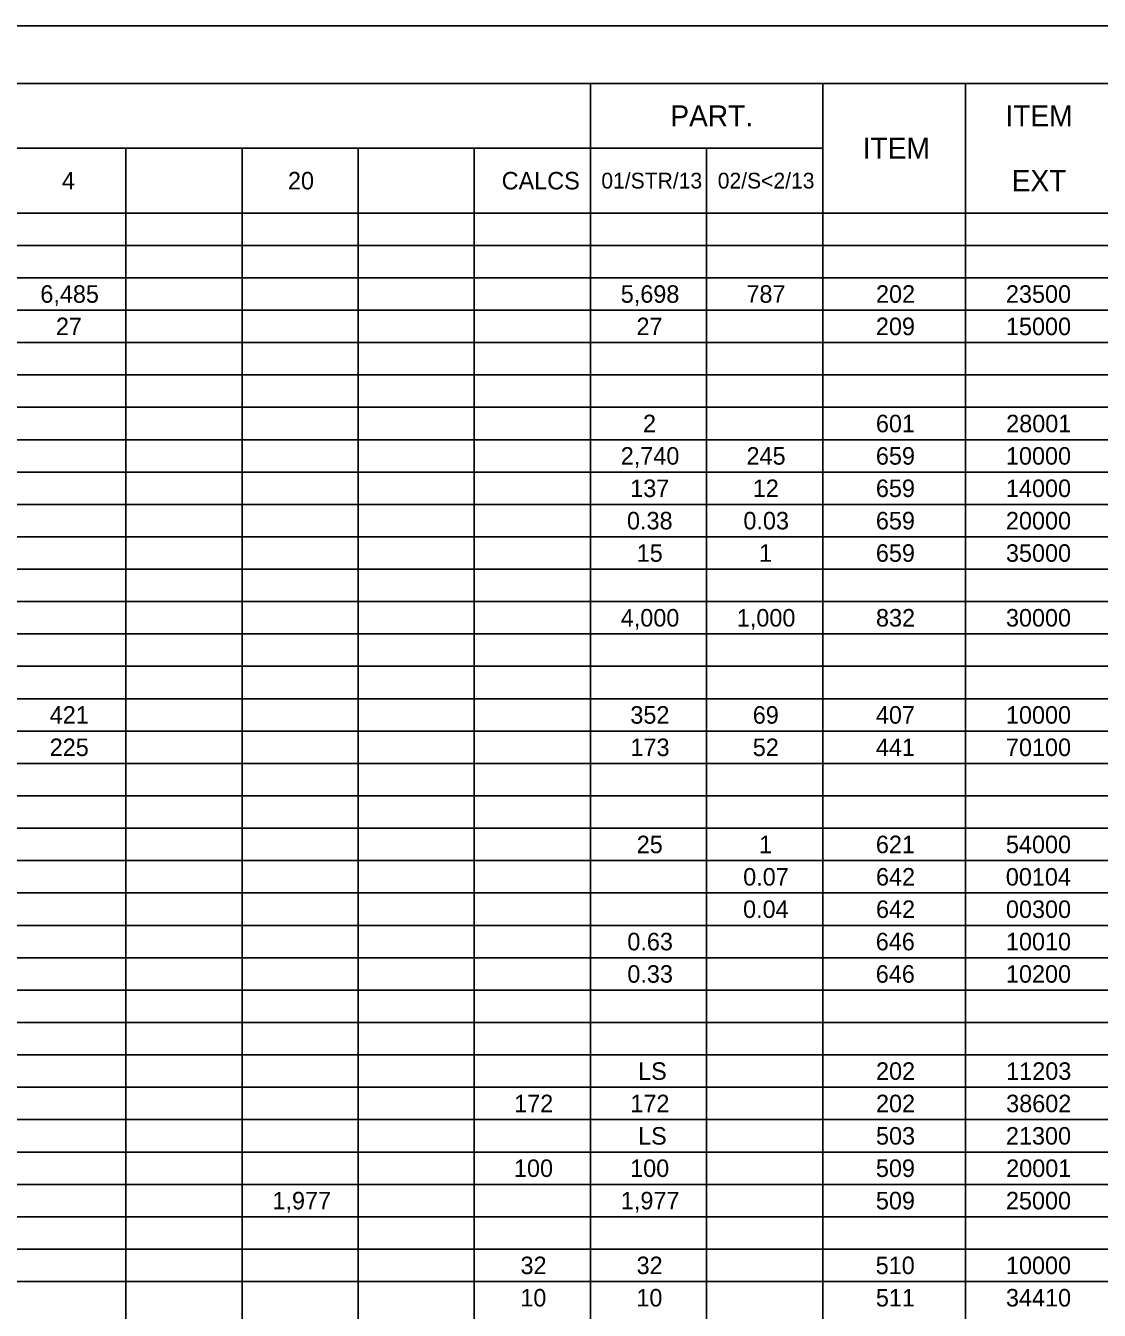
# Model space of a CAD drawing. Extents: x -58.2 to 35.9, y -5.7 to 34.4.
# Drawn here: x 8.67 to 17.96, y 10.89 to 22 of the extents above; entities that cross this region are included whole.
import ezdxf

# ---------------------------------------------------------------- set-up
doc = ezdxf.new("R2010")
doc.units = 0
for name, color, linetype in [('Default', 7, 'Continuous'), ('SH_Border', 7, 'Continuous'), ('SH_Cut_Line', 7, 'Continuous')]:
    doc.layers.add(name, color=color, linetype=linetype)

msp = doc.modelspace()

# ---------------------------------------------------------------- linework, layer by layer
at = {"layer": 'Default'}
for p, q in [((1.5, 21.5), (32, 21.5)), ((13.555, 21.5), (13.555, 0.5)), ((15.564, 21.5), (15.564, 0.5)), ((16.799, 21.5), (16.799, 0.5)), ((1.5, 20.94), (15.564, 20.94)), ((9.537, 20.94), (9.537, 0.5)), ((10.541, 20.94), (10.541, 0.5)), ((11.546, 20.94), (11.546, 0.5)), ((12.55, 20.94), (12.55, 0.5)), ((14.56, 20.94), (14.56, 0.5)), ((1.5, 20.38), (32, 20.38)), ((1.5, 20.1), (32, 20.1)), ((1.5, 19.82), (32, 19.82)), ((1.5, 19.54), (32, 19.54)), ((1.5, 19.26), (32, 19.26)), ((1.5, 18.98), (32, 18.98)), ((1.5, 18.7), (32, 18.7)), ((1.5, 18.42), (32, 18.42)), ((1.5, 18.14), (32, 18.14)), ((1.5, 17.86), (32, 17.86)), ((1.5, 17.58), (32, 17.58)), ((1.5, 17.3), (32, 17.3)), ((1.5, 17.02), (32, 17.02)), ((1.5, 16.74), (32, 16.74)), ((1.5, 16.46), (32, 16.46)), ((1.5, 16.18), (32, 16.18)), ((1.5, 15.9), (32, 15.9)), ((1.5, 15.62), (32, 15.62)), ((1.5, 15.34), (32, 15.34)), ((1.5, 15.06), (32, 15.06)), ((1.5, 14.78), (32, 14.78)), ((1.5, 14.5), (32, 14.5)), ((1.5, 14.22), (32, 14.22)), ((1.5, 13.94), (32, 13.94)), ((1.5, 13.66), (32, 13.66)), ((1.5, 13.38), (32, 13.38)), ((1.5, 13.1), (32, 13.1)), ((1.5, 12.82), (32, 12.82)), ((1.5, 12.54), (32, 12.54)), ((1.5, 12.26), (32, 12.26)), ((1.5, 11.98), (32, 11.98)), ((1.5, 11.7), (32, 11.7)), ((1.5, 11.42), (32, 11.42)), ((1.5, 11.14), (32, 11.14))]:
    msp.add_line(p, q, dxfattribs=at)
at = {"layer": 'SH_Border'}
msp.add_lwpolyline([(1.5, 21.5), (33.5, 21.5), (33.5, 0.5), (1.5, 0.5)], close=True, dxfattribs=at)
at = {"layer": 'SH_Cut_Line'}
msp.add_lwpolyline([(0, 0), (34, 0), (34, 22), (0, 22)], close=True, dxfattribs=at)

# ---------------------------------------------------------------- texts
at = {"layer": 'Default'}
for s, height, p in [('PART.', 0.1818, (14.246, 21.129)), ('ITEM', 0.1818, (17.145, 21.129)), ('ITEM', 0.1818, (15.91, 20.849)), ('4', 0.152, (8.983, 20.584)), ('20', 0.1515, (10.938, 20.584)), ('CALCS', 0.1515, (12.787, 20.584)), ('01/STR/13', 0.1364, (13.649, 20.592)), ('02/S<2/13', 0.1364, (14.656, 20.592)), ('EXT', 0.1818, (17.199, 20.569)), ('6,485', 0.1515, (8.796, 19.604)), ('5,698', 0.1515, (13.817, 19.604)), ('787', 0.1515, (14.904, 19.604)), ('202', 0.1515, (16.025, 19.604)), ('23500', 0.1515, (17.149, 19.604)), ('27', 0.1515, (8.931, 19.324)), ('27', 0.1515, (13.953, 19.324)), ('209', 0.1515, (16.024, 19.324)), ('15000', 0.1515, (17.149, 19.324)), ('2', 0.152, (14.009, 18.484)), ('601', 0.1515, (16.024, 18.484)), ('28001', 0.1515, (17.151, 18.484)), ('2,740', 0.1515, (13.817, 18.204)), ('245', 0.1515, (14.905, 18.204)), ('659', 0.1515, (16.024, 18.204)), ('10000', 0.1515, (17.149, 18.204)), ('137', 0.1515, (13.899, 17.924)), ('12', 0.1515, (14.959, 17.924)), ('659', 0.1515, (16.024, 17.924)), ('14000', 0.1515, (17.149, 17.924)), ('0.38', 0.1515, (13.871, 17.644)), ('0.03', 0.1515, (14.878, 17.644)), ('659', 0.1515, (16.024, 17.644)), ('20000', 0.1515, (17.149, 17.644)), ('15', 0.1515, (13.955, 17.364)), ('1', 0.152, (15.013, 17.364)), ('659', 0.1515, (16.024, 17.364)), ('35000', 0.1515, (17.149, 17.364)), ('4,000', 0.1515, (13.817, 16.804)), ('1,000', 0.1515, (14.821, 16.804)), ('832', 0.1515, (16.025, 16.804)), ('30000', 0.1515, (17.149, 16.804)), ('421', 0.1515, (8.877, 15.964)), ('352', 0.1515, (13.9, 15.964)), ('69', 0.1515, (14.959, 15.964)), ('407', 0.1515, (16.024, 15.964)), ('10000', 0.1515, (17.149, 15.964)), ('225', 0.1515, (8.877, 15.684)), ('173', 0.1515, (13.901, 15.684)), ('52', 0.1515, (14.959, 15.684)), ('441', 0.1515, (16.024, 15.684)), ('70100', 0.1515, (17.149, 15.684)), ('25', 0.1515, (13.955, 14.844)), ('621', 0.1515, (16.024, 14.844)), ('54000', 0.1515, (17.149, 14.844)), ('1', 0.152, (15.013, 14.844)), ('0.07', 0.1515, (14.876, 14.564)), ('642', 0.1515, (16.025, 14.564)), ('00104', 0.1515, (17.148, 14.564)), ('0.04', 0.1515, (14.875, 14.284)), ('642', 0.1515, (16.025, 14.284)), ('00300', 0.1515, (17.149, 14.284)), ('0.63', 0.1515, (13.874, 14.004)), ('646', 0.1515, (16.023, 14.004)), ('10010', 0.1515, (17.149, 14.004)), ('0.33', 0.1515, (13.874, 13.724)), ('646', 0.1515, (16.023, 13.724)), ('10200', 0.1515, (17.149, 13.724)), ('LS', 0.1515, (13.967, 12.884)), ('202', 0.1515, (16.025, 12.884)), ('11203', 0.1515, (17.151, 12.884)), ('172', 0.1515, (12.895, 12.604)), ('172', 0.1515, (13.9, 12.604)), ('202', 0.1515, (16.025, 12.604)), ('38602', 0.1515, (17.151, 12.604)), ('LS', 0.1515, (13.967, 12.324)), ('503', 0.1515, (16.025, 12.324)), ('21300', 0.1515, (17.149, 12.324)), ('100', 0.1515, (12.893, 12.044)), ('100', 0.1515, (13.898, 12.044)), ('509', 0.1515, (16.024, 12.044)), ('20001', 0.1515, (17.151, 12.044)), ('1,977', 0.1515, (10.804, 11.764)), ('1,977', 0.1515, (13.818, 11.764)), ('509', 0.1515, (16.024, 11.764)), ('25000', 0.1515, (17.149, 11.764)), ('32', 0.1515, (12.95, 11.204)), ('32', 0.1515, (13.954, 11.204)), ('510', 0.1515, (16.022, 11.204)), ('10000', 0.1515, (17.149, 11.204)), ('10', 0.1515, (12.948, 10.924)), ('10', 0.1515, (13.952, 10.924)), ('511', 0.1515, (16.024, 10.924)), ('34410', 0.1515, (17.149, 10.924))]:
    msp.add_text(s, height=height, dxfattribs=at).set_placement(p)

doc.saveas('drawing.dxf')
